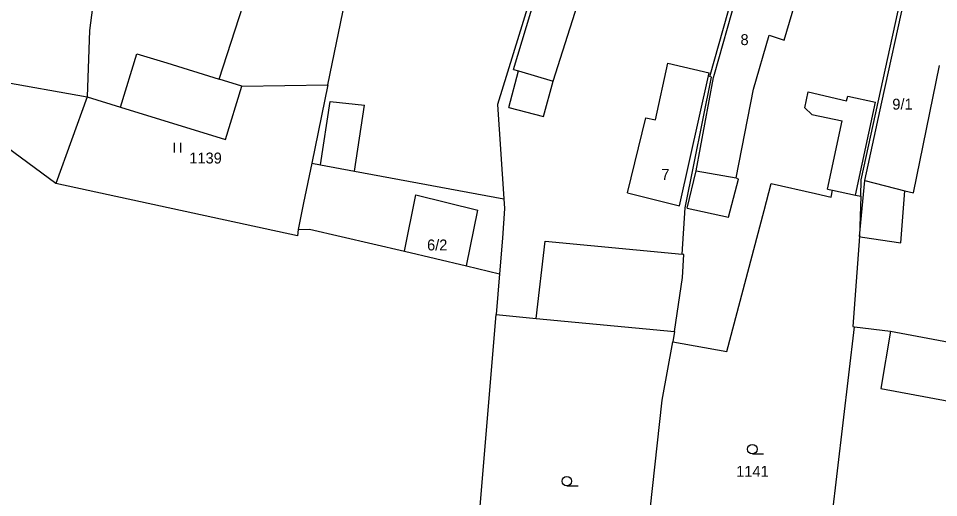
# Model space of a CAD drawing. Extents: x -746176 to -739709, y -1128407 to -1124482.
# Drawn here: x -742377 to -742233.7, y -1126240.2 to -1126165.6 of the extents above; entities that cross this region are included whole.
import ezdxf

# ---------------------------------------------------------------- set-up
doc = ezdxf.new("R2010")
doc.units = 0
for name, color, linetype in [('Hranice parcel', 7, 'Continuous'), ('Parcelní čísla', 7, 'Continuous'), ('Vnitřní kresba', 7, 'Continuous'), ('Značky kultur', 7, 'Continuous')]:
    doc.layers.add(name, color=color, linetype=linetype)

msp = doc.modelspace()

# ---------------------------------------------------------------- linework, layer by layer
at = {"layer": 'Hranice parcel'}
for p, q in [((-742408.55, -1126170.19), (-742366.28, -1126177.8)), ((-742342.18, -1126176.09), (-742328.77, -1126175.93)), ((-742328.77, -1126175.93), (-742331.28, -1126188.11)), ((-742366.28, -1126177.8), (-742371.13, -1126191.3)), ((-742331.28, -1126188.11), (-742332.55, -1126194.28)), ((-742332.55, -1126194.28), (-742333.4, -1126198.44)), ((-742302.07, -1126205.33), (-742302.59, -1126211.7)), ((-742253.45, -1126270.36), (-742246.8, -1126213.59)), ((-742274.79, -1126214.34), (-742275.09, -1126215.95))]:
    msp.add_line(p, q, dxfattribs=at)
for points in [[(-742351.14, -1126116.55), (-742363.54, -1126149.51), (-742365.92, -1126167.47), (-742366.28, -1126177.8)], [(-742342.18, -1126176.09), (-742345.69, -1126175.02), (-742337.62, -1126150), (-742335.33, -1126150.55), (-742330.35, -1126135.4), (-742326.7, -1126125.8)], [(-742328.77, -1126175.93), (-742325.75, -1126161.24), (-742314.45, -1126130.46)], [(-742290.03, -1126139.66), (-742294.39, -1126153.07), (-742302.36, -1126178.95), (-742301.38, -1126193.67)], [(-742274.79, -1126214.34), (-742273.54, -1126205.94), (-742273.34, -1126202.32), (-742273.6, -1126202.3), (-742273.12, -1126195.05), (-742269.02, -1126174.69), (-742269.3, -1126174.61), (-742265.06, -1126159.49), (-742261.84, -1126150.05)], [(-742245.81, -1126193.24), (-742245.74, -1126190.69), (-742238.52, -1126157.67)], [(-742366.28, -1126177.8), (-742361.05, -1126179.41), (-742344.7, -1126184.42), (-742342.18, -1126176.09)], [(-742371.13, -1126191.3), (-742382.1, -1126183.23), (-742395.78, -1126181.85), (-742403.65, -1126182.31), (-742424.12, -1126188.09), (-742455.22, -1126201.03)], [(-742331.28, -1126188.11), (-742329.94, -1126188.36), (-742324.62, -1126189.35), (-742301.38, -1126193.67)], [(-742333.4, -1126198.44), (-742333.49, -1126199.45), (-742371.13, -1126191.3)], [(-742275.09, -1126215.95), (-742266.66, -1126217.47), (-742260.87, -1126195.48), (-742259.76, -1126191.3), (-742252.85, -1126192.83), (-742250.39, -1126193.38), (-742250.2, -1126192.33), (-742246.63, -1126193.07), (-742245.81, -1126193.24)], [(-742301.38, -1126193.67), (-742301.28, -1126195.16), (-742301.61, -1126199.8), (-742302.07, -1126205.33)], [(-742245.81, -1126193.24), (-742245.98, -1126199.54), (-742247.06, -1126213.57), (-742246.8, -1126213.59)], [(-742333.4, -1126198.44), (-742331.66, -1126198.39), (-742316.87, -1126201.82), (-742307.21, -1126204.11), (-742302.07, -1126205.33)], [(-742281.72, -1126273.18), (-742307.41, -1126266.17), (-742306.81, -1126260.62), (-742305.51, -1126247.12), (-742302.59, -1126211.7)], [(-742302.59, -1126211.7), (-742296.36, -1126212.29), (-742274.79, -1126214.34)], [(-742246.8, -1126213.59), (-742241.16, -1126214.28), (-742242.7, -1126223.21), (-742217.86, -1126227.84)], [(-742281.72, -1126273.18), (-742280.8, -1126262.02), (-742276.72, -1126225.02), (-742275.09, -1126215.95)]]:
    msp.add_lwpolyline(points, dxfattribs=at)
at = {"layer": 'Vnitřní kresba'}
for p, q in [((-742293.68, -1126175.34), (-742283.2, -1126142.1)), ((-742299.86, -1126173.52), (-742293.82, -1126153.25)), ((-742242.53, -1126178.6), (-742237.95, -1126157.86)), ((-742268.58, -1126174.24), (-742264.5, -1126159.68)), ((-742257.72, -1126168.93), (-742256.05, -1126163.36)), ((-742262.5, -1126176.58), (-742260.05, -1126168.17)), ((-742260.05, -1126168.17), (-742257.72, -1126168.93)), ((-742361.05, -1126179.41), (-742358.51, -1126171.1)), ((-742358.51, -1126171.1), (-742353.86, -1126172.49)), ((-742353.86, -1126172.49), (-742345.69, -1126175.02)), ((-742277.79, -1126181.37), (-742275.84, -1126172.55)), ((-742275.84, -1126172.55), (-742269.42, -1126174.05)), ((-742300.61, -1126179.42), (-742299.11, -1126173.74)), ((-742299.86, -1126173.52), (-742299.11, -1126173.74)), ((-742299.11, -1126173.74), (-742293.68, -1126175.34)), ((-742274.02, -1126194.74), (-742269.42, -1126174.05)), ((-742237.59, -1126192.75), (-742233.53, -1126172.88)), ((-742295.23, -1126180.82), (-742293.68, -1126175.34)), ((-742271.45, -1126189.28), (-742268.73, -1126174.77)), ((-742268.73, -1126174.77), (-742268.58, -1126174.24)), ((-742265.2, -1126190.4), (-742262.5, -1126176.58)), ((-742254.53, -1126179.5), (-742254.01, -1126176.99)), ((-742254.01, -1126176.99), (-742248, -1126178.41)), ((-742248, -1126178.41), (-742247.84, -1126177.67)), ((-742247.84, -1126177.67), (-742243.51, -1126178.62)), ((-742329.94, -1126188.36), (-742328.41, -1126178.52)), ((-742328.41, -1126178.52), (-742323.05, -1126179.05)), ((-742324.62, -1126189.35), (-742323.05, -1126179.05)), ((-742300.61, -1126179.42), (-742295.23, -1126180.82)), ((-742254.53, -1126179.5), (-742253.42, -1126180.51)), ((-742246.63, -1126193.07), (-742243.51, -1126178.62)), ((-742245.16, -1126190.83), (-742242.53, -1126178.6)), ((-742282.11, -1126192.72), (-742279.25, -1126181.03)), ((-742279.25, -1126181.03), (-742277.79, -1126181.37)), ((-742253.42, -1126180.51), (-742248.68, -1126181.54)), ((-742250.98, -1126192.17), (-742248.68, -1126181.54)), ((-742272.83, -1126195.11), (-742271.45, -1126189.28)), ((-742271.45, -1126189.28), (-742265.2, -1126190.4)), ((-742266.38, -1126196.53), (-742264.83, -1126190.6)), ((-742265.2, -1126190.4), (-742264.83, -1126190.6)), ((-742245.98, -1126199.54), (-742245.16, -1126190.83)), ((-742245.16, -1126190.83), (-742238.94, -1126192.41)), ((-742282.11, -1126192.72), (-742274.02, -1126194.74)), ((-742250.98, -1126192.17), (-742250.2, -1126192.33)), ((-742239.56, -1126200.52), (-742238.94, -1126192.41)), ((-742238.94, -1126192.41), (-742237.59, -1126192.75)), ((-742316.87, -1126201.82), (-742315.09, -1126193.06)), ((-742315.09, -1126193.06), (-742305.41, -1126195.41)), ((-742307.21, -1126204.11), (-742305.41, -1126195.41)), ((-742272.83, -1126195.11), (-742266.38, -1126196.53)), ((-742245.98, -1126199.54), (-742245.51, -1126199.61)), ((-742245.51, -1126199.61), (-742239.56, -1126200.52)), ((-742296.36, -1126212.29), (-742294.97, -1126200.25)), ((-742294.97, -1126200.25), (-742273.6, -1126202.3)), ((-742241.16, -1126214.28), (-742226.13, -1126217.11))]:
    msp.add_line(p, q, dxfattribs=at)
at = {"layer": 'Značky kultur'}
for p, q in [((-742352.65, -1126186.46), (-742352.65, -1126184.96)), ((-742351.65, -1126186.46), (-742351.65, -1126184.96)), ((-742262.68, -1126233.41), (-742260.93, -1126233.41)), ((-742291.57, -1126238.39), (-742289.82, -1126238.39))]:
    msp.add_line(p, q, dxfattribs=at)
for centre in [(-742262.68, -1126232.66), (-742291.57, -1126237.64)]:
    msp.add_circle(centre, 0.75, dxfattribs=at)

# ---------------------------------------------------------------- texts
at = {"layer": 'Parcelní čísla'}
for s, p in [('8', (-742264.53, -1126169.72)), ('9/1', (-742240.89, -1126179.77)), ('1139', (-742350.35, -1126188.16)), ('7', (-742276.85, -1126190.71)), ('6/2', (-742313.33, -1126201.7)), ('1141', (-742265.2, -1126236.96))]:
    msp.add_text(s, height=1.7, dxfattribs=at).set_placement(p)

doc.saveas('drawing.dxf')
